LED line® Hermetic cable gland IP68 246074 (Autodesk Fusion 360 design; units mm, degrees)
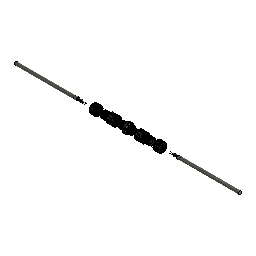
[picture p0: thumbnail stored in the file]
sketch "Sketch1" plane through (0, 0, 0) normal (0, 1, 0) x axis (1, 0, 0)
  circle C1 centre (0, 0) radius 7
  circle C2 centre (0, 0) radius 11.5
  point P1 (0, 0)
  point P2 (0, 0)
  point P3 (0, 0)
  coincident P1 P2
  coincident P1 P3
  dimension "d1" diameter C1 = 14
  dimension "d2" diameter C2 = 23
extrude "Extrude1" new body sketch "Sketch1" along normal blind 3 bodies "nakretka 1"
fillet "Fillet1" radius 2
sketch "Sketch2" plane through (0, 3, 0) normal (0, 1, 0) x axis (-1, 0, 0)
  circle C1 centre (0, 0) radius 7
  circle C2 centre (0, 0) radius 11.5
  circle C3 centre (0, 0) radius 12.5
  concentric C1 C3
  dimension "d7" diameter C3 = 25
extrude "Extrude2" add sketch "Sketch2" along normal blind 13
sketch "Sketch3" plane through (0, 3, 0) normal (0, -1, 0) x axis (1, 0, 0)
  line L1 (0, 12.5) -> (0, 0)
  line L2 (0, 11.55) -> (0, 12.5)
  line L3 (5.5, 11.55) -> (0, 11.55)
  line L4 (-6.7433, 11.55) -> (0, 11.55)
  line L5 (-13.3742, -0.0648) -> (-10.0026, 5.775)
  line L6 (-7.2526, 10.5381) -> (-10.0026, 5.775)
  line L7 (-10.0026, 5.775) -> (-10.8253, 6.25)
  line L8 (-6.631, -11.6148) -> (-10.0026, -5.775)
  line L9 (-12.7526, -1.0119) -> (-10.0026, -5.775)
  line L10 (-10.0026, -5.775) -> (-10.8253, -6.25)
  line L11 (6.7433, -11.55) -> (0, -11.55)
  line L12 (-5.5, -11.55) -> (0, -11.55)
  line L13 (0, -11.55) -> (0, -12.5)
  line L14 (13.3742, 0.0648) -> (10.0026, -5.775)
  line L15 (7.2526, -10.5381) -> (10.0026, -5.775)
  line L16 (10.0026, -5.775) -> (10.8253, -6.25)
  line L17 (6.631, 11.6148) -> (10.0026, 5.775)
  line L18 (12.7526, 1.0119) -> (10.0026, 5.775)
  line L19 (10.0026, 5.775) -> (10.8253, 6.25)
  circle C1 centre (0, 0) radius 12.5
  circle C2 centre (0, 0) radius 11.5
  point P2 (0, 0)
  point P3 (0, 0)
  point P4 (0, 12.5)
  point P5 (0, 11.55)
  coincident P2 P3
  coincident C1 P4
  vertical L1
  parallel L1 L2
  perpendicular L1 L3
  perpendicular L2 L4
  dimension "d10" distance P4 P5 = 0.95
  dimension "d12" C-Pattern1-Angle = 360
extrude "Extrude3" cut sketch "Sketch3" profile of C1 L1 L2 L3 L4 L5 L6 L7 L8 L9 L10 L11 L12 L13 L14 L15 L16 L17 L18 L19 against normal blind 11
sketch "Sketch4" plane through (0, 16, 0) normal (0, 1, 0) x axis (-1, 0, 0)
  circle C1 centre (0, 0) radius 7
  circle C2 centre (0, 0) radius 12.5
  circle C3 centre (0, 0) radius 10
  point P1 (0, 0)
  point P3 (0, 0)
  coincident P1 P3
  dimension "d15" diameter C3 = 20
extrude "Extrude4" cut sketch "Sketch4" profile of C1 C3 against normal blind 13
sketch "Sketch5" plane through (0, 0, 0) normal (0, 0, 1) x axis (1, 0, 0)
  line L1 (7, 1.5) -> (7, 0)
  line L2 (10, 3) -> (7, 1.5)
  line L3 (6.2096, 3.4993) -> (10, 3)
  line L4 (7, 1.5) -> (6.2096, 3.4993)
  point P2 (7, 0)
  point P3 (7, 1.5)
  vertical L1
  dimension "d18" distance P2 P3 = 1.5
sweep "Sweep1" sketch "Sketch5" TwistAngle 0 TaperAngle 0
thread "Thread1"
sketch "Sketch6" plane through (0, 16, 0) normal (0, 1, 0) x axis (-1, 0, 0)
  curve K1 (-7.7193, 6.7632) -> (-2.8802, -10.7214)
  curve K2 (2.8802, -10.7214) -> (7.7193, 6.7632)
  arc A1 centre (0, 0) radius 10.263 clockwise from (-7.7193, 6.7632) to (7.7193, 6.7632)
  arc A2 centre (0, 0) radius 11.1015 clockwise from (2.8802, -10.7214) to (-2.8802, -10.7214)
  circle C1 centre (0, 0) radius 12.5
  circle C2 centre (0, 0) radius 11
  point P1 (0, 0)
  point P7 (0, 0)
  coincident P1 P7
  dimension "d25" diameter C2 = 22
extrude "Extrude5" cut sketch "Sketch6" profile of K1 A1 K2 C2 against normal blind 0.5
sketch "Sketch7" plane through (0, 16, 0) normal (0, 1, 0) x axis (-1, 0, 0)
  curve K1 (2.8802, -10.7214) -> (5.3499, -9.6114)
  curve K2 (-5.3499, -9.6114) -> (-2.8802, -10.7214)
  arc A1 centre (0, 0) radius 11 clockwise from (-5.3499, -9.6114) to (5.3499, -9.6114)
  arc A2 centre (0, 0) radius 11.1015 clockwise from (2.8802, -10.7214) to (-2.8802, -10.7214)
  circle C1 centre (0, 0) radius 12.5
  circle C2 centre (0, -11.7291) radius 0.2247
  circle C3 centre (8.2937, -8.2937) radius 0.2247
  circle C4 centre (11.7291, 0) radius 0.2247
  circle C5 centre (8.2937, 8.2937) radius 0.2247
  circle C6 centre (0, 11.7291) radius 0.2247
  circle C7 centre (-8.2937, 8.2937) radius 0.2247
  circle C8 centre (-11.7291, 0) radius 0.2247
  circle C9 centre (-8.2937, -8.2937) radius 0.2247
  dimension "d29" C-Pattern1-Angle = 360
extrude "Extrude6" cut sketch "Sketch7" profile of C2 C3 C4 C5 C6 C7 C8 C9 against normal blind 0.5
work_plane "WorkPlane1" AlongDistance 1
sketch "Sketch8" plane through (0, 17, 0) normal (0, 1, 0) x axis (1, 0, 0)
  line L1 (0, 12) -> (0, 0)
  line L2 (6.5, 12) -> (-6.5093, 12)
  line L3 (-3.8891, 13.0815) -> (-13.0881, 3.8825)
  line L4 (-12, 6.5) -> (-12, -6.5093)
  line L5 (-13.0815, -3.8891) -> (-3.8825, -13.0881)
  line L6 (-6.5, -12) -> (6.5093, -12)
  line L7 (3.8891, -13.0815) -> (13.0881, -3.8825)
  line L8 (12, -6.5) -> (12, 6.5093)
  line L9 (13.0815, 3.8891) -> (3.8825, 13.0881)
  circle C1 centre (0, 0) radius 13
  point P1 (0, 0)
  point P2 (0, 0)
  point P3 (0, 0)
  point P4 (0, 12)
  coincident P1 P2
  coincident P1 P3
  vertical L1
  perpendicular L1 L2
  dimension "d33" diameter C1 = 26
  dimension "d34" distance P3 P4 = 12
  dimension "d36" C-Pattern1-Angle = 360
extrude "Extrude7" new body sketch "Sketch8" profile of L2 L3 L4 L5 L6 L7 L8 L9 along normal blind 18 bodies "nakretka2"
sketch "Sketch9" plane through (0, 17, 0) normal (0, -1, 0) x axis (1, 0, 0)
  line L1 (-4.9706, -12) -> (-12, -4.9706)
  line L2 (4.9706, -12) -> (-4.9706, -12)
  line L3 (12, -4.9706) -> (4.9706, -12)
  line L4 (12, 4.9706) -> (12, -4.9706)
  line L5 (4.9706, 12) -> (12, 4.9706)
  line L6 (-4.9706, 12) -> (4.9706, 12)
  line L7 (-12, 4.9706) -> (-4.9706, 12)
  line L8 (-12, -4.9706) -> (-12, 4.9706)
  circle C1 centre (0, 0) radius 11
  point P1 (0, 0)
  point P10 (0, 0)
  coincident P1 P10
  dimension "d39" diameter C1 = 22
extrude "Extrude8" add sketch "Sketch9" profile of C1 along normal blind 18
fillet "Fillet2" radius 0.5
thread "Thread2" ThreadOffset 0 ThreadLength 9
sketch "Sketch10" plane through (0, -1, 0) normal (0, -1, 0) x axis (1, 0, 0)
  circle C1 centre (0, 0) radius 9.925
  circle C2 centre (0, 0) radius 9.25
  point P1 (0, 0)
  point P3 (0, 0)
  coincident P1 P3
  dimension "d46" diameter C2 = 18.5
extrude "Extrude9" cut sketch "Sketch10" against normal blind 9
sketch "Sketch11" plane through (0, -1, 0) normal (0, -1, 0) x axis (1, 0, 0)
  circle C1 centre (0, 0) radius 9.25
  circle C2 centre (0, 0) radius 4.5
  concentric C1 C2
  dimension "d49" diameter C2 = 9
extrude "Extrude10" cut sketch "Sketch11" profile of C2 against normal blind 45
sketch "Sketch12" plane through (0, -1, 0) normal (0, -1, 0) x axis (1, 0, 0)
  line L1 (-1.343, 7.6328) -> (-0.0073, 9.25)
  line L2 (0.5244, 7.7322) -> (1.6547, 9.1008)
  line L3 (-4.3314, 6.4266) -> (-3.769, 8.4473)
  line L4 (-2.6659, 7.277) -> (-2.19, 8.987)
  line L5 (-6.5709, 4.1093) -> (-6.8789, 6.1841)
  line L6 (-5.3953, 5.5636) -> (-5.656, 7.3193)
  line L7 (-7.6742, 1.0814) -> (-8.7995, 2.8515)
  line L8 (-7.1917, 2.8881) -> (-8.144, 4.386)
  line L9 (-7.4506, -2.1335) -> (-9.1986, -0.9741)
  line L10 (-7.7447, -0.2867) -> (-9.2239, 0.6944)
  line L11 (-5.9387, -4.9794) -> (-8.0071, -4.6313)
  line L12 (-6.9585, -3.412) -> (-8.7089, -3.1174)
  line L13 (-3.3999, -6.9644) -> (-5.4311, -7.4877)
  line L14 (-4.9691, -5.9473) -> (-6.688, -6.3901)
  line L15 (-0.2733, -7.7452) -> (-1.9161, -9.0494)
  line L16 (-2.1206, -7.4542) -> (-3.5107, -8.5579)
  line L17 (2.9006, -7.1867) -> (1.9303, -9.0464)
  line L18 (1.0947, -7.6723) -> (0.2736, -9.246)
  line L19 (5.5729, -5.3856) -> (5.4429, -7.4791)
  line L20 (4.1206, -6.5637) -> (4.0106, -8.3353)
  line L21 (7.2817, -2.6533) -> (8.0144, -4.6187)
  line L22 (6.4341, -4.3203) -> (7.0542, -5.9834)
  line L23 (7.7313, 0.5378) -> (9.2001, -0.9597)
  line L24 (7.6351, -1.3298) -> (8.878, -2.597)
  line L25 (6.8442, 3.6359) -> (8.795, 2.8653)
  line L26 (7.5158, 1.8907) -> (9.1667, 1.2386)
  line L27 (4.7736, 6.1053) -> (6.8692, 6.1949)
  line L28 (6.0971, 4.7842) -> (7.8704, 4.8599)
  line L29 (1.8776, 7.5191) -> (3.7557, 8.4532)
  line L30 (3.624, 6.8505) -> (5.2133, 7.6409)
  circle C1 centre (0, 0) radius 4.5
  circle C2 centre (0, 0) radius 9.25
  circle C3 centre (0, 0) radius 7.75
  point P4 (-0.0073, 9.25)
  point P5 (-1.343, 7.6328)
  point P6 (1.6547, 9.1008)
  point P7 (0.5244, 7.7322)
  concentric C1 C3
  coincident C2 P4
  coincident C3 P5
  coincident C2 P6
  coincident C3 P7
  parallel L1 L2
  dimension "d52" diameter C3 = 15.5
  dimension "d54" C-Pattern1-Angle = 360
extrude "Extrude11" cut sketch "Sketch12" profile of C2 C3 L1 L2 L3 L4 L5 L6 L7 L8 L9 L10 L11 L12 L13 L14 L15 L16 L17 L18 L19 L20 L21 L22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 against normal blind 8
extrude "Extrude12" cut sketch "Sketch12" profile of C1 C3 against normal blind 8
work_plane "WorkPlane2" sketch "Sketch12" AlongDistance -3
extrude "Extrude13" new body sketch "Sketch12" profile of C1 C3 against normal blind 8
sketch "Sketch13" plane through (0, 0, 0) normal (1, 0, 0) x axis (0, 0, -1)
  line L1 (4.5, 1.5) -> (4.5, -1)
  line L2 (4.8617, 1.5) -> (4.5, 1.5)
  line L3 (7.5, -1) -> (4.8617, 1.5)
  line L4 (7.5, -1) -> (4.5, -1)
  point P2 (4.5, -1)
  point P3 (4.5, 1.5)
  vertical L1
  perpendicular L1 L2
  perpendicular L1 L4
  dimension "d62" distance P2 P3 = 2.5
sweep "Sweep2" sketch "Sketch13" TwistAngle 0 TaperAngle 0
combine "Combine1"
work_plane "WorkPlane3" AlongDistance -1
split "Split1"
thread "Thread3" ThreadOffset 0.5 ThreadLength 16
combine "Combine2"
sketch "Sketch14" plane through (0, 0, 0) normal (1, 0, 0) x axis (0, 0, -1)
  line L1 (4.5, 16) -> (9, 18)
  line L2 (4.5, 18.2677) -> (4.5, 16)
  line L3 (9, 18) -> (4.5, 18.2677)
  vertical L2
sweep "Sweep3" sketch "Sketch14" TwistAngle 0 TaperAngle 0
move "Move1"
work_plane "WorkPlane4" AlongDistance 5.4
sketch "Sketch15" plane through (0, 42.4, 0) normal (0, 1, 0) x axis (1, 0, 0)
  line L1 (0, 12) -> (0, 0)
  line L2 (-1, 12) -> (0, 12)
  line L3 (-8, 12) -> (-1, 12)
  line L4 (0, 12) -> (-8, 12)
  line L5 (6, 12) -> (0, 12)
  line L6 (-7.3923, 11.1962) -> (-10.3923, 6)
  line L7 (-10.3923, 6) -> (-14.3923, -0.9282)
  line L8 (-13.3923, -0.8038) -> (-10.3923, -6)
  line L9 (-10.3923, -6) -> (-6.3923, -12.9282)
  line L10 (-6, -12) -> (0, -12)
  line L11 (0, -12) -> (8, -12)
  line L12 (7.3923, -11.1962) -> (10.3923, -6)
  line L13 (10.3923, -6) -> (14.3923, 0.9282)
  line L14 (13.3923, 0.8038) -> (10.3923, 6)
  line L15 (10.3923, 6) -> (6.3923, 12.9282)
  circle C1 centre (0, 0) radius 13
  point P1 (0, 0)
  point P2 (0, 0)
  point P3 (0, 0)
  point P4 (0, 12)
  coincident P1 P2
  coincident P2 P3
  vertical L1
  perpendicular L1 L2
  parallel L2 L3
  perpendicular L1 L5
  dimension "d79" diameter C1 = 26
  dimension "d80" distance P3 P4 = 12
  dimension "d82" C-Pattern1-Angle = 360
extrude "Extrude14" new body sketch "Sketch15" profile of C1 L2 L3 L4 L5 L6 L7 L8 L9 L10 L11 L12 L13 L14 L15 along normal blind 3
sketch "Sketch16" plane through (0, 45.4, 0) normal (0, 1, 0) x axis (-1, 0, 0)
  line L1 (5, -12) -> (-5, -12)
  line L2 (12.8923, -1.6699) -> (7.8923, -10.3301)
  line L3 (7.8923, 10.3301) -> (12.8923, 1.6699)
  line L4 (-5, 12) -> (5, 12)
  line L5 (-12.8923, 1.6699) -> (-7.8923, 10.3301)
  line L6 (-7.8923, -10.3301) -> (-12.8923, -1.6699)
  arc A1 centre (0, 0) radius 13 clockwise from (-5, -12) to (-7.8923, -10.3301)
  arc A2 centre (0, 0) radius 13 clockwise from (7.8923, -10.3301) to (5, -12)
  arc A3 centre (0, 0) radius 13 clockwise from (12.8923, 1.6699) to (12.8923, -1.6699)
  arc A4 centre (0, 0) radius 13 clockwise from (5, 12) to (7.8923, 10.3301)
  arc A5 centre (0, 0) radius 13 clockwise from (-7.8923, 10.3301) to (-5, 12)
  arc A6 centre (0, 0) radius 13 clockwise from (-12.8923, -1.6699) to (-12.8923, 1.6699)
  circle C1 centre (0, 0) radius 10.5
  circle C2 centre (0, 0) radius 10
  point P1 (0, 0)
  point P15 (0, 0)
  coincident P1 P15
  concentric C1 C2
  dimension "d85" diameter C1 = 21
  dimension "d86" diameter C2 = 20
extrude "Extrude15" add sketch "Sketch16" profile of C1 C2 along normal blind 8.5
extrude "Extrude16" cut sketch "Sketch16" profile of C1 C2 along normal blind 2
step "TorusPrimitive" MinorDiameter 2 MajorDiameter 20 bodies "uszczelka1"
move "Move2"
thread "Thread4" ThreadOffset 0 ThreadLength 6.5
sketch "Sketch18" plane through (0, 53.9, 0) normal (0, 1, 0) x axis (-1, 0, 0)
  curve K1 (-9.8989, -0.7191) -> (3.7642, 8.2503)
  curve K2 (9.0271, -0.8652) -> (-5.5723, -8.2131)
  line L1 (10.5, 0) -> (0, 0)
  line L2 (10.5, -4.5) -> (10.5, 0)
  line L3 (7.2309, -4.5) -> (10.5, -4.5)
  line L4 (7.2309, 4.5) -> (7.2309, -4.5)
  line L5 (10.5, 4.5) -> (7.2309, 4.5)
  line L6 (10.5, -4.5) -> (10.5, 4.5)
  line L7 (-7.5126, 4.0122) -> (0.2817, 8.5122)
  line L8 (0.2817, 8.5122) -> (-1.3529, 11.3433)
  line L9 (-1.3529, 11.3433) -> (-5.25, 9.0933)
  line L10 (-9.1471, 6.8433) -> (-7.5126, 4.0122)
  line L11 (-1.3529, 11.3433) -> (-9.1471, 6.8433)
  line L12 (0.2817, -8.5122) -> (-7.5126, -4.0122)
  line L13 (-7.5126, -4.0122) -> (-9.1471, -6.8433)
  line L14 (-9.1471, -6.8433) -> (-5.25, -9.0933)
  line L15 (-1.3529, -11.3433) -> (0.2817, -8.5122)
  line L16 (-9.1471, -6.8433) -> (-1.3529, -11.3433)
  arc A1 centre (0, 0) radius 9.925 clockwise from (-5.5723, -8.2131) to (-9.8989, -0.7191)
  arc A2 centre (0, 0) radius 9.0685 clockwise from (3.7642, 8.2503) to (9.0271, -0.8652)
  circle C1 centre (0, 0) radius 9
  point P7 (0, 0)
  point P8 (0, 0)
  point P9 (10.5, 0)
  point P10 (10.5, -4.5)
  point P13 (10.5, 4.5)
  concentric A1 C1
  coincident P7 P8
  horizontal L1
  perpendicular L1 L2
  horizontal L3
  vertical L4
  horizontal L5
  vertical L6
  dimension "d95" diameter C1 = 18
  dimension "d96" distance P9 P10 = 4.5
  dimension "d97" distance P10 P13 = 9
  dimension "d99" C-Pattern1-Angle = 360
extrude "Extrude17" cut sketch "Sketch18" profile of C1 L1 L3 L4 L5 L7 L8 L10 L12 L13 L15 against normal blind 8.5
extrude "Extrude18" cut sketch "Sketch18" against normal blind 6.5
sketch "Sketch19" plane through (0, 45.4, 0) normal (0, 1, 0) x axis (-1, 0, 0)
  line L1 (9, 0) -> (0, 0)
  line L2 (0, 4.5) -> (0, 0)
  line L3 (0.5, 4.5) -> (0, 4.5)
  line L4 (8.8, 4.5) -> (0.5, 4.5)
  line L5 (9, 0) -> (8.8, 4.5)
  line L6 (8.8, -4.5) -> (0.5, -4.5)
  line L7 (9, 0) -> (8.8, -4.5)
  line L8 (0, -4.5) -> (0, 0)
  line L9 (0.5, -4.5) -> (0, -4.5)
  line L10 (-8.2971, 5.371) -> (-4.1471, -1.817)
  line L11 (-4.5, 7.7942) -> (-8.2971, 5.371)
  line L12 (-4.5, 7.7942) -> (-0.5029, 9.871)
  line L13 (-0.5029, 9.871) -> (3.6471, 2.683)
  line L14 (3.6471, 2.683) -> (3.8971, 2.25)
  line L15 (-4.1471, -1.817) -> (-3.8971, -2.25)
  line L16 (-0.5029, -9.871) -> (3.6471, -2.683)
  line L17 (-4.5, -7.7942) -> (-0.5029, -9.871)
  line L18 (-4.5, -7.7942) -> (-8.2971, -5.371)
  line L19 (-8.2971, -5.371) -> (-4.1471, 1.817)
  line L20 (-4.1471, 1.817) -> (-3.8971, 2.25)
  line L21 (3.6471, -2.683) -> (3.8971, -2.25)
  circle C1 centre (0, 0) radius 9
  point P2 (0, 0)
  point P3 (0, 0)
  point P4 (9, 0)
  point P11 (0, 0)
  point P10 (9, 0)
  point P5 (0, 4.5)
  point P12 (0, -4.5)
  point P6 (0.5, 4.5)
  point P8 (0.5, -4.5)
  point P7 (8.8, 4.5)
  point P9 (8.8, -4.5)
  coincident P2 P3
  coincident C1 P4
  horizontal L1
  perpendicular L1 L2
  perpendicular L2 L3
  perpendicular L2 L4
  symmetric P3 L1 P11
  symmetric P4 L1 P10
  symmetric L1 P5 P12
  symmetric L1 P6 P8
  symmetric L1 P7 P9
  dimension "d105" C-Pattern1-Angle = 360
extrude "Extrude19" new body sketch "Sketch19" profile of C1 L1 L2 L3 L4 L5 L6 L7 L8 L9 L10 L11 L12 L13 L16 L17 L18 L19 along normal blind 12
delete_face "DeleteFace1"
delete_face "DeleteFace2"
delete_face "DeleteFace3"
sketch "Sketch20" plane through (0, 57.4, 0) normal (0, 1, 0) x axis (-1, 0, 0)
  line L1 (9, 0) -> (8.8, -4.5)
  line L2 (8.8, 4.5) -> (9, 0)
  line L3 (2.5981, 4.5) -> (8.8, 4.5)
  line L4 (-0.5029, 9.871) -> (2.5981, 4.5)
  line L5 (-4.5, 7.7942) -> (-0.5029, 9.871)
  line L6 (-8.2971, 5.371) -> (-4.5, 7.7942)
  line L7 (-5.1962, 0) -> (-8.2971, 5.371)
  line L8 (-8.2971, -5.371) -> (-5.1962, 0)
  line L9 (-4.5, -7.7942) -> (-8.2971, -5.371)
  line L10 (-0.5029, -9.871) -> (-4.5, -7.7942)
  line L11 (2.5981, -4.5) -> (-0.5029, -9.871)
  line L12 (8.8, -4.5) -> (2.5981, -4.5)
  line L13 (3, -2.3492) -> (3, 0)
  line L14 (7, -2.3492) -> (3, -2.3492)
  line L15 (7, 0) -> (7, -2.3492)
  line L16 (3, 0) -> (7, 0)
  line L17 (3, 2.3492) -> (3, 0)
  line L18 (7, 2.3492) -> (3, 2.3492)
  line L19 (7, 0) -> (7, 2.3492)
  line L20 (-5.5345, 4.8876) -> (-3.5345, 1.4235)
  line L21 (-3.5, 6.0622) -> (-5.5345, 4.8876)
  line L22 (-3.5345, 1.4235) -> (-1.5, 2.5981)
  line L23 (-3.5, 6.0622) -> (-1.4655, 7.2368)
  line L24 (-1.4655, 7.2368) -> (0.5345, 3.7727)
  line L25 (0.5345, 3.7727) -> (-1.5, 2.5981)
  line L26 (-1.4655, -7.2368) -> (0.5345, -3.7727)
  line L27 (-3.5, -6.0622) -> (-1.4655, -7.2368)
  line L28 (0.5345, -3.7727) -> (-1.5, -2.5981)
  line L29 (-3.5, -6.0622) -> (-5.5345, -4.8876)
  line L30 (-5.5345, -4.8876) -> (-3.5345, -1.4235)
  line L31 (-3.5345, -1.4235) -> (-1.5, -2.5981)
  point P14 (3, 0)
  point P18 (3, 0)
  point P15 (3, -2.3492)
  point P19 (3, 2.3492)
  point P16 (7, -2.3492)
  point P20 (7, 2.3492)
  point P17 (7, 0)
  point P21 (7, 0)
  perpendicular L3 L13
  perpendicular L13 L14
  perpendicular L3 L15
  perpendicular L13 L16
  symmetric P14 L16 P18
  symmetric P15 L16 P19
  symmetric P16 L16 P20
  symmetric P17 L16 P21
  dimension "d109" C-Pattern1-Angle = 360
extrude "Extrude20" cut sketch "Sketch20" profile of L13 L14 L15 L16 L17 L18 L19 L20 L21 L22 L23 L24 L25 L26 L27 L28 L29 L30 L31 against normal blind 10
chamfer "Chamfer1" distance 1
fillet "Fillet3" radius 1.5
sketch "Sketch21" plane through (0, 45.4, 0) normal (0, 1, 0) x axis (-1, 0, 0)
  circle C1 centre (0, 0) radius 9
  circle C2 centre (0, 0) radius 6.7082
  concentric C1 C2
extrude "Extrude21" cut sketch "Sketch21" profile of C2 along normal blind 10
extrude "Extrude22" new body of existing geometry blind 10
sketch "Sketch22" plane through (0, 45.4, 0) normal (0, 1, 0) x axis (-1, 0, 0)
  line L1 (-9, 0) -> (0, 0)
  line L2 (0, 0) -> (-9, 0)
  line L3 (0, -0.25) -> (0, 0)
  line L4 (-9, -0.25) -> (0, -0.25)
  line L5 (-9, 0) -> (-9, -0.25)
  line L6 (-9, 0.25) -> (0, 0.25)
  line L7 (-9, 0) -> (-9, 0.25)
  line L8 (0, 0.25) -> (0, 0)
  line L9 (4.7165, -7.6692) -> (0.2165, 0.125)
  line L10 (4.2835, -7.9192) -> (-0.2165, -0.125)
  line L11 (4.5, -7.7942) -> (4.2835, -7.9192)
  line L12 (4.5, -7.7942) -> (4.7165, -7.6692)
  line L13 (4.2835, 7.9192) -> (-0.2165, 0.125)
  line L14 (4.7165, 7.6692) -> (0.2165, -0.125)
  line L15 (4.5, 7.7942) -> (4.7165, 7.6692)
  line L16 (4.5, 7.7942) -> (4.2835, 7.9192)
  circle C1 centre (0, 0) radius 9
  point P1 (0, 0)
  point P3 (0, 0)
  point P4 (-9, 0)
  point P10 (-9, 0)
  point P5 (0, 0)
  point P11 (0, 0)
  point P6 (0, -0.25)
  point P8 (0, 0.25)
  point P7 (-9, -0.25)
  point P9 (-9, 0.25)
  coincident P1 P3
  coincident C1 P4
  horizontal L1
  horizontal L2
  vertical L3
  horizontal L4
  vertical L5
  symmetric P4 L2 P10
  symmetric P5 L2 P11
  symmetric P6 L2 P8
  symmetric P7 L2 P9
  dimension "d119" distance P4 P7 = 0.25
  dimension "d121" C-Pattern1-Angle = 360
extrude "Extrude23" new body sketch "Sketch22" profile of C1 L1 L2 L3 L4 L6 L8 L9 L10 L13 L14 along normal blind 8.5
combine "Combine3"
combine "Combine4"
sketch "Sketch23" plane through (0, 0, 0) normal (0, 0, 1) x axis (1, 0, 0)
  curve K1 (-9.5, 55.8431) -> (-1.5, 57.5)
  curve K2 (-10.0653, 55.4125) -> (-8.9347, 56.2737)
  line L1 (-8.7797, 58.9091) -> (-1.5, 57.5)
  line L2 (-9.5, 55.8431) -> (-8.7797, 58.9091)
  point P3 (-9.5, 55.8431)
  midpoint P3 K2
sweep "Sweep4" sketch "Sketch23" TwistAngle 0 TaperAngle 0
remove_body "RemoveBody1"
remove_body "RemoveBody2"
remove_body "RemoveBody3"
remove_body "RemoveBody4"
remove_body "RemoveBody5"
remove_body "RemoveBody6"
work_plane "WorkPlane5" AlongDistance -9
sketch "Sketch24" plane through (-9, 0, 0) normal (1, 0, 0) x axis (0, 0, -1)
  line L1 (2, 48) -> (0, 48)
  line L2 (2, 58) -> (2, 48)
  line L3 (2.8, 58) -> (2, 58)
  line L4 (2.8, 45.5702) -> (2.8, 58)
  line L5 (2, 45.5702) -> (2.8, 45.5702)
  line L6 (2, 58) -> (2, 45.5702)
  line L7 (0, 45.4) -> (0, 56.1865)
  line L8 (-2, 58) -> (-2, 48)
  line L9 (-2, 58) -> (-2, 45.5702)
  line L10 (-2.8, 45.5702) -> (-2.8, 58)
  line L11 (-2.8, 58) -> (-2, 58)
  line L12 (-2, 45.5702) -> (-2.8, 45.5702)
  line L13 (-2, 53) -> (2, 53)
  line L14 (-2, 58.5927) -> (-2, 53)
  line L15 (2, 58.5927) -> (-2, 58.5927)
  line L16 (2, 53) -> (2, 58.5927)
  line L17 (2, 58) -> (2.8, 58)
  line L18 (2, 62) -> (2, 58)
  line L19 (2.8, 62) -> (2, 62)
  line L20 (2.8, 58) -> (2.8, 62)
  line L21 (-2, 58) -> (-2.8, 58)
  line L22 (-2, 62.3112) -> (-2, 58)
  line L23 (-2.8, 62.3112) -> (-2, 62.3112)
  line L24 (-2.8, 58) -> (-2.8, 62.3112)
  line L25 (-2, 55) -> (2, 55)
  line L26 (-2, 62) -> (-2, 55)
  line L27 (2, 62) -> (-2, 62)
  line L28 (2, 55) -> (2, 62)
  point P3 (2, 48)
  point P10 (-2, 48)
  point P4 (2, 58)
  point P11 (-2, 58)
  point P5 (2.8, 58)
  point P13 (-2.8, 58)
  point P6 (2.8, 45.5702)
  point P14 (-2.8, 45.5702)
  point P7 (2, 45.5702)
  point P12 (-2, 45.5702)
  point P15 (2, 53)
  point P27 (-2, 62)
  point P25 (2, 55)
  horizontal L1
  perpendicular L1 L2
  horizontal L3
  vertical L4
  horizontal L5
  vertical L6
  symmetric P3 L7 P10
  symmetric P4 L7 P11
  symmetric P5 L7 P13
  symmetric P6 L7 P14
  symmetric P7 L7 P12
  horizontal L13
  vertical L14
  horizontal L15
  vertical L16
  midpoint L2 P15
  horizontal L17
  vertical L18
  horizontal L19
  vertical L20
  horizontal L21
  vertical L22
  horizontal L23
  vertical L24
  horizontal L25
  vertical L26
  horizontal L27
  vertical L28
  coincident L22 P27
  coincident L16 P25
  dimension "d131" distance P4 P5 = 0.8
work_plane "WorkPlane6" AlongDistance 0
split "Split2"
move "Move3"
extrude "Extrude24" new body of existing geometry blind 2
combine "Combine5"
move "Move4"
extrude "Extrude25" new body of existing geometry blind 1
extrude "Extrude26" new body of existing geometry blind 3
combine "Combine6"
combine "Combine7"
combine "Combine8"
combine "Combine9"
combine "Combine10"
combine "Combine11"
sketch "Sketch25" plane through (0, 42.4, 0) normal (0, -1, 0) x axis (1, 0, 0)
  line L1 (12.8923, -1.6699) -> (7.8923, -10.3301)
  line L2 (7.8923, 10.3301) -> (12.8923, 1.6699)
  line L3 (-5, 12) -> (5, 12)
  line L4 (-12.8923, 1.6699) -> (-7.8923, 10.3301)
  line L5 (-7.8923, -10.3301) -> (-12.8923, -1.6699)
  line L6 (5, -12) -> (-5, -12)
  arc A1 centre (0, 0) radius 13 clockwise from (7.8923, -10.3301) to (5, -12)
  arc A2 centre (0, 0) radius 13 clockwise from (12.8923, 1.6699) to (12.8923, -1.6699)
  arc A3 centre (0, 0) radius 13 clockwise from (5, 12) to (7.8923, 10.3301)
  arc A4 centre (0, 0) radius 13 clockwise from (-7.8923, 10.3301) to (-5, 12)
  arc A5 centre (0, 0) radius 13 clockwise from (-12.8923, -1.6699) to (-12.8923, 1.6699)
  arc A6 centre (0, 0) radius 13 clockwise from (-5, -12) to (-7.8923, -10.3301)
  point P4 (0, 0)
  point P15 (0, 0)
  coincident P4 P15
extrude "Extrude27" new body sketch "Sketch24" profile of L2 L3 L4 L5 L6 L8 L9 L10 L11 L12 L14 L15 L16 L17 L18 L19 L20 L21 L22 L23 L24 L25 L26 L27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 along normal blind 1
circular_pattern "C-Pattern1" TotalAngle 360
split "Split3"
sketch "Sketch26" plane through (-8, 0, 0) normal (-1, 0, 0) x axis (0, 0, 1)
  curve K1 (2.8, 59.476) -> (-2.8, 59.476)
  line L1 (-2.8, 45.5702) -> (-2.8, 59.476)
  line L2 (-2, 45.5702) -> (-2.8, 45.5702)
  line L3 (-2, 55) -> (-2, 45.5702)
  line L4 (2, 55) -> (-2, 55)
  line L5 (2, 45.5702) -> (2, 55)
  line L6 (2.8, 45.5702) -> (2, 45.5702)
  line L7 (2.8, 59.476) -> (2.8, 45.5702)
extrude "Extrude28" new body sketch "Sketch26" along normal blind 1.2
split "Split4"
sketch "Sketch27" plane through (0, 0, 0) normal (0, 0, -1) x axis (-1, 0, 0)
  line L1 (9.2, 55) -> (8, 55)
  line L2 (9.2, 59.6882) -> (9.2, 55)
  line L3 (9.2, 59.6882) -> (8, 59.6882)
  line L4 (8, 55) -> (8, 59.6882)
  curve K1 (8.2, 59.3) -> (9.2, 59.6882)
  point P4 (9.2, 59.6882)
  point P6 (9.2, 59.6882)
  point P7 (8, 59.4756)
  coincident P4 P6
  coincident L4 P7
extrude "Extrude29" cut sketch "Sketch27" profile of L3 L4 K1 against normal blind 2.8
delete_face "DeleteFace4"
chamfer "Chamfer2" distance 0.4
sketch "Sketch28" plane through (0, 0, 2) normal (0, 0, -1) x axis (-1, 0, 0)
  line L1 (8, 45.5702) -> (8, 55)
  line L2 (9.2, 45.5702) -> (8, 45.5702)
  line L3 (9.2, 55.4) -> (9.2, 45.5702)
  line L4 (8.8, 55) -> (9.2, 55.4)
  line L5 (8, 55) -> (8.8, 55)
  line L6 (8.8, 45.1849) -> (8.8, 55)
  point P6 (8.8, 55)
  point P7 (8.8, 55)
  coincident P6 P7
  perpendicular L2 L6
extrude "Extrude30" cut sketch "Sketch28" profile of L2 L3 L4 L6 against normal blind 1
sketch "Sketch29" plane through (0, 0, 2) normal (0, 0, -1) x axis (-1, 0, 0)
  line L1 (8.8, 55) -> (8.8, 45.5702)
  line L2 (8, 55) -> (8.8, 55)
  line L3 (8, 45.5702) -> (8, 55)
  line L4 (8.8, 45.5702) -> (8, 45.5702)
  line L5 (4.5876, 50.7089) -> (8, 56)
  line L6 (4.5876, 45.5702) -> (4.5876, 50.7089)
  line L7 (8, 45.5702) -> (4.5876, 45.5702)
  line L8 (8, 45.5702) -> (8, 56)
  point P5 (8, 45.5702)
  point P9 (8, 45.5702)
  perpendicular L4 L6
  coincident P5 P9
  perpendicular L3 L7
extrude "Extrude31" add sketch "Sketch29" profile of L3 L5 L6 L7 L8 against normal blind 0.8
mirror "Mirror1" mirrorStitchTolerance 0.1
sketch "Sketch30" plane through (0, 0, -2.8) normal (0, 0, -1) x axis (-1, 0, 0)
  line L1 (9.2, 55.4) -> (8.8, 55)
  line L2 (9.2, 59.6882) -> (9.2, 55.4)
  curve K1 (8, 59.4756) -> (9.2, 59.6882)
  line L3 (8, 56) -> (8, 59.4756)
  line L4 (4.5876, 50.7089) -> (8, 56)
  line L5 (4.5876, 45.5702) -> (4.5876, 50.7089)
  line L6 (8.8, 45.5702) -> (4.5876, 45.5702)
  line L7 (8.8, 55) -> (8.8, 45.5702)
  line L8 (7.273, 45.5702) -> (8.8, 52.0102)
  point P10 (8.8, 52.0102)
  point P11 (7.273, 45.5702)
  coincident L7 P10
  coincident L6 P11
extrude "Extrude32" cut sketch "Sketch30" profile of L6 L7 L8 against normal blind 13
remove_body "RemoveBody7"
remove_body "RemoveBody8"
remove_body "RemoveBody9"
remove_body "RemoveBody10"
remove_body "RemoveBody11"
remove_body "RemoveBody12"
remove_body "RemoveBody13"
circular_pattern "C-Pattern2" TotalAngle 360
sketch "Sketch31" plane through (4.6, 0, 7.9674) normal (0.5, 0, 0.866) x axis (0.866, 0, -0.5)
  line L1 (2.8, 55.4) -> (-2.8, 55.4)
  line L2 (2.8, 59.6882) -> (2.8, 55.4)
  line L3 (2.8, 59.6882) -> (0, 59.6882)
  line L4 (-2.8, 59.6882) -> (0, 59.6882)
  line L5 (-2.8, 55.4) -> (-2.8, 59.6882)
  curve K1
  curve K2
  curve K3
  curve K4
extrude "Extrude33" new body sketch "Sketch31" along normal blind 0.3
sketch "Sketch32" plane through (-9.2, 0, 0) normal (-1, 0, 0) x axis (0, 0, 1)
  line L1 (2.8, 55.4) -> (-2.8, 55.4)
  line L2 (2.8, 59.6882) -> (2.8, 55.4)
  line L3 (2.8, 59.6882) -> (0, 59.6882)
  line L4 (-2.8, 59.6882) -> (0, 59.6882)
  line L5 (-2.8, 55.4) -> (-2.8, 59.6882)
  curve K1
  curve K2
  curve K3
  curve K4
extrude "Extrude34" new body sketch "Sketch32" along normal blind 0.3
move "Move5"
move "Move6"
sketch "Sketch33" plane through (4.6, 0, -7.9674) normal (0.5, 0, -0.866) x axis (-0.866, 0, -0.5)
  line L1 (2.8, 55.4) -> (-2.8, 55.4)
  line L2 (2.8, 59.6882) -> (2.8, 55.4)
  line L3 (2.8, 59.6882) -> (0, 59.6882)
  line L4 (-2.8, 59.6882) -> (0, 59.6882)
  line L5 (-2.8, 55.4) -> (-2.8, 59.6882)
  line L6 (0.2, 58.6) -> (0, 58.6)
  line L7 (0.2, 56.1) -> (0.2, 58.6)
  line L8 (0, 56.1) -> (0.2, 56.1)
  line L9 (0, 58.6) -> (0, 56.1)
  line L10 (0.6609, 58.6) -> (0.2, 58.6)
  line L11 (0.6609, 58.4574) -> (0.6609, 58.6)
  line L12 (0.2, 58.4574) -> (0.6609, 58.4574)
  line L13 (0.2, 58.6) -> (0.2, 58.4574)
  line L14 (1, 58.1) -> (0.2, 58.1)
  line L15 (1, 57.9) -> (1, 58.1)
  line L16 (0.2, 57.9) -> (1, 57.9)
  line L17 (0.2, 58.1) -> (0.2, 57.9)
  line L18 (1.2, 57.4358) -> (0.2, 57.4358)
  line L19 (1.2, 57.6) -> (1.2, 57.4358)
  line L20 (0.2, 57.6) -> (1.2, 57.6)
  line L21 (0.2, 57.4358) -> (0.2, 57.6)
  circle C1 centre (0, 57.4358) radius 1.7982
  circle C2 centre (0, 57.4358) radius 1.5928
  point P16 (0.2, 58.1)
  point P20 (0.2, 57.4358)
  concentric C1 C2
  horizontal L6
  vertical L7
  horizontal L8
  vertical L9
  horizontal L10
  vertical L11
  horizontal L12
  vertical L13
  horizontal L14
  vertical L15
  horizontal L16
  vertical L17
  coincident L7 P16
  horizontal L18
  vertical L19
  horizontal L20
  vertical L21
  coincident L7 P20
extrude "Extrude35" new body sketch "Sketch33" profile of C1 C2 L6 L7 L8 L9 L10 L11 L12 L13 L14 L15 L16 L17 L18 L19 L20 L21 along normal blind 0.3
mirror "Mirror2" mirrorStitchTolerance 0.1
sketch "Sketch34" plane through (4.75, 0, -8.2272) normal (0.5, 0, -0.866) x axis (-0.866, 0, -0.5)
  line L1 (1.2, 57.4358) -> (0.2, 57.4358)
  line L2 (1.2, 57.6) -> (1.2, 57.4358)
  line L3 (0.2, 57.6) -> (1.2, 57.6)
  line L4 (0.2, 57.9) -> (0.2, 57.6)
  line L5 (1, 57.9) -> (0.2, 57.9)
  line L6 (1, 58.1) -> (1, 57.9)
  line L7 (0.2, 58.1) -> (1, 58.1)
  line L8 (0.2, 58.4574) -> (0.2, 58.1)
  line L9 (0.6609, 58.4574) -> (0.2, 58.4574)
  line L10 (0.6609, 58.6) -> (0.6609, 58.4574)
  line L11 (-0.6609, 58.6) -> (0.6609, 58.6)
  line L12 (-0.6609, 58.4574) -> (-0.6609, 58.6)
  line L13 (-0.2, 58.4574) -> (-0.6609, 58.4574)
  line L14 (-0.2, 58.1) -> (-0.2, 58.4574)
  line L15 (-1, 58.1) -> (-0.2, 58.1)
  line L16 (-1, 57.9) -> (-1, 58.1)
  line L17 (-0.2, 57.9) -> (-1, 57.9)
  line L18 (-0.2, 57.6) -> (-0.2, 57.9)
  line L19 (-1.2, 57.6) -> (-0.2, 57.6)
  line L20 (-1.2, 57.4358) -> (-1.2, 57.6)
  line L21 (-0.2, 57.4358) -> (-1.2, 57.4358)
  line L22 (-0.2, 56.1) -> (-0.2, 57.4358)
  line L23 (0.2, 56.1) -> (-0.2, 56.1)
  line L24 (0.2, 57.4358) -> (0.2, 56.1)
  line L25 (0.3, 58.4574) -> (-0.2, 58.4574)
  line L26 (0.3, 58.1) -> (0.3, 58.4574)
  line L27 (-0.2, 58.1) -> (0.3, 58.1)
  line L28 (-0.2, 58.4574) -> (-0.2, 58.1)
  line L29 (0.3, 57.9) -> (-0.3, 57.9)
  line L30 (0.3, 57.6) -> (0.3, 57.9)
  line L31 (-0.3, 57.6) -> (0.3, 57.6)
  line L32 (-0.3, 57.9) -> (-0.3, 57.6)
  point P28 (0.3, 58.1)
  point P15 (-0.2, 58.4574)
  point P26 (-0.2, 58.4574)
  point P32 (0.3, 57.6)
  point P30 (-0.3, 57.9)
  horizontal L25
  vertical L26
  horizontal L27
  vertical L28
  coincident L7 P28
  coincident P15 P26
  horizontal L29
  vertical L30
  horizontal L31
  vertical L32
  coincident L3 P32
  coincident L17 P30
extrude "Extrude36" cut sketch "Sketch34" profile of L3 L4 L5 L7 L8 L9 L14 L18 L25 L26 L27 L28 L29 L30 L31 against normal blind 0.6
sketch "Sketch35" plane through (4.75, 0, -8.2272) normal (0.5, 0, -0.866) x axis (-0.866, 0, -0.5)
  line L1 (-1.2, 57.6) -> (1.2, 57.6)
  line L2 (-1.2, 57.4358) -> (-1.2, 57.6)
  line L3 (-0.2, 57.4358) -> (-1.2, 57.4358)
  line L4 (-0.2, 56.1) -> (-0.2, 57.4358)
  line L5 (0.2, 56.1) -> (-0.2, 56.1)
  line L6 (0.2, 57.4358) -> (0.2, 56.1)
  line L7 (1.2, 57.4358) -> (0.2, 57.4358)
  line L8 (1.2, 57.6) -> (1.2, 57.4358)
  line L9 (-0.1, 57.4358) -> (-0.2, 57.4358)
  line L10 (-0.1, 56) -> (-0.1, 57.4358)
  line L11 (-0.2, 56) -> (-0.1, 56)
  line L12 (-0.2, 57.4358) -> (-0.2, 56)
  point P5 (-0.2, 57.4358)
  point P10 (-0.2, 57.4358)
  horizontal L9
  vertical L10
  horizontal L11
  vertical L12
  coincident P5 P10
extrude "Extrude37" cut sketch "Sketch35" profile of L4 L5 L9 L10 L12 against normal blind 0.3
sketch "Sketch36" plane through (4.75, 0, -8.2272) normal (0.5, 0, -0.866) x axis (-0.866, 0, -0.5)
  line L1 (-0.1, 56.1) -> (-0.1, 57.4358)
  line L2 (0.2, 56.1) -> (-0.1, 56.1)
  line L3 (0.2, 57.4358) -> (0.2, 56.1)
  line L4 (1.2, 57.4358) -> (0.2, 57.4358)
  line L5 (1.2, 57.6) -> (1.2, 57.4358)
  line L6 (-1.2, 57.6) -> (1.2, 57.6)
  line L7 (-1.2, 57.4358) -> (-1.2, 57.6)
  line L8 (-0.1, 57.4358) -> (-1.2, 57.4358)
  line L9 (0, 57.4358) -> (-0.1, 57.4358)
  line L10 (0.1, 57.4358) -> (0, 57.4358)
  line L11 (0.2, 57.4358) -> (0.1, 57.4358)
  line L12 (0.1, 56.1) -> (0.1, 57.4358)
  point P2 (-0.1, 57.4358)
  point P10 (-0.1, 57.4358)
  point P5 (0.2, 57.4358)
  point P13 (0.2, 57.4358)
  point P14 (0.1, 56.1)
  coincident P2 P10
  perpendicular L1 L9
  perpendicular L1 L10
  coincident P5 P13
  coincident L2 P14
  perpendicular L2 L12
extrude "Extrude38" cut sketch "Sketch36" profile of L2 L3 L11 L12 against normal blind 0.4
scale "Scale1" ScaleFactor 0.7
move "Move7"
mirror "Mirror3" mirrorStitchTolerance 0.1 bodies "nakretka 1 (1)", "nakretka2 (1)"
mirror "Mirror4" mirrorStitchTolerance 0.1 bodies "uszczelka2"
combine "Combine12"
combine "Combine13"
move "Move8"
combine "Combine14"
combine "Combine15"
combine "Combine16"
combine "Combine17"
remove_body "RemoveBody14"
remove_body "RemoveBody15"
remove_body "RemoveBody16"
remove_body "RemoveBody17"
remove_body "RemoveBody18"
split "Split5"
mirror "Mirror5" mirrorStitchTolerance 0.1
combine "Combine18"
combine "Combine19"
move "Move9"
combine "Combine20"
move "Move10"
combine "Combine21"
move "Move11"
move "Move12"
move "Move13"
move "Move14"
move "Move15"
move "Move16"
move "Move17"
sketch "Sketch37" plane through (0, 0, 0) normal (1, 0, 0) x axis (0, 0, -1)
  circle C1 centre (0, 47.5) radius 4.272
extrude "Extrude39" new body sketch "Sketch37" against normal blind 170 and along normal blind 4 bodies "kabel"
move "Move18"
sketch "Sketch38" plane through (-106, 0, 0) normal (1, 0, 0) x axis (0, 0, -1)
  circle C1 centre (0, 47.5) radius 4.272
  circle C2 centre (0, 47.5) radius 2.9596
  concentric C1 C2
extrude "Extrude40" cut sketch "Sketch38" against normal blind 37
sketch "Sketch39" plane through (-106, 0, 0) normal (1, 0, 0) x axis (0, 0, -1)
  circle C1 centre (0, 47.5) radius 2.9596
  circle C2 centre (0, 49.5) radius 0.8301
  circle C3 centre (0, 49.5) radius 0.452
  circle C4 centre (-1.7321, 46.5) radius 0.8301
  circle C5 centre (-1.7321, 46.5) radius 0.452
  circle C6 centre (1.7321, 46.5) radius 0.8301
  circle C7 centre (1.7321, 46.5) radius 0.452
  concentric C2 C3
  dimension "d186" C-Pattern1-Angle = 360
extrude "Extrude41" add sketch "Sketch39" profile of C3 C5 C7 along normal blind 18
extrude "Extrude42" add sketch "Sketch39" profile of C2 C3 C4 C5 C6 C7 along normal blind 12
extrude "Extrude43" add of existing geometry blind 34
extrude "Extrude44" add sketch "Sketch39" profile of C1 C2 C4 C6 along normal blind 8
sketch "Sketch40" plane through (-109, 0, 0) normal (1, 0, 0) x axis (0, 0, -1)
  circle C1 centre (0, 47.5) radius 2.9596
  circle C2 centre (0, 47.5) radius 4.272
  circle C3 centre (0, 47.5) radius 3.1401
  concentric C1 C3
extrude "Extrude45" cut sketch "Sketch40" profile of C1 C3 against normal blind 7.7
work_plane "WorkPlane7" AlongDistance -3
mirror "Mirror6" mirrorStitchTolerance 0.1 bodies "kabel (1)"
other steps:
step "Ё    Ā⟾    ܁    Ā⠀    ഁ" bodies "nakretka 1", "nakretka2", "uszczelka1", "nakretka 1 (1)", "nakretka2 (1)"
named bodies: "nakretka 1", "nakretka2", "uszczelka1", "nakretka 1 (1)", "nakretka2 (1)", "uszczelka2", "kabel", "kabel (1)"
